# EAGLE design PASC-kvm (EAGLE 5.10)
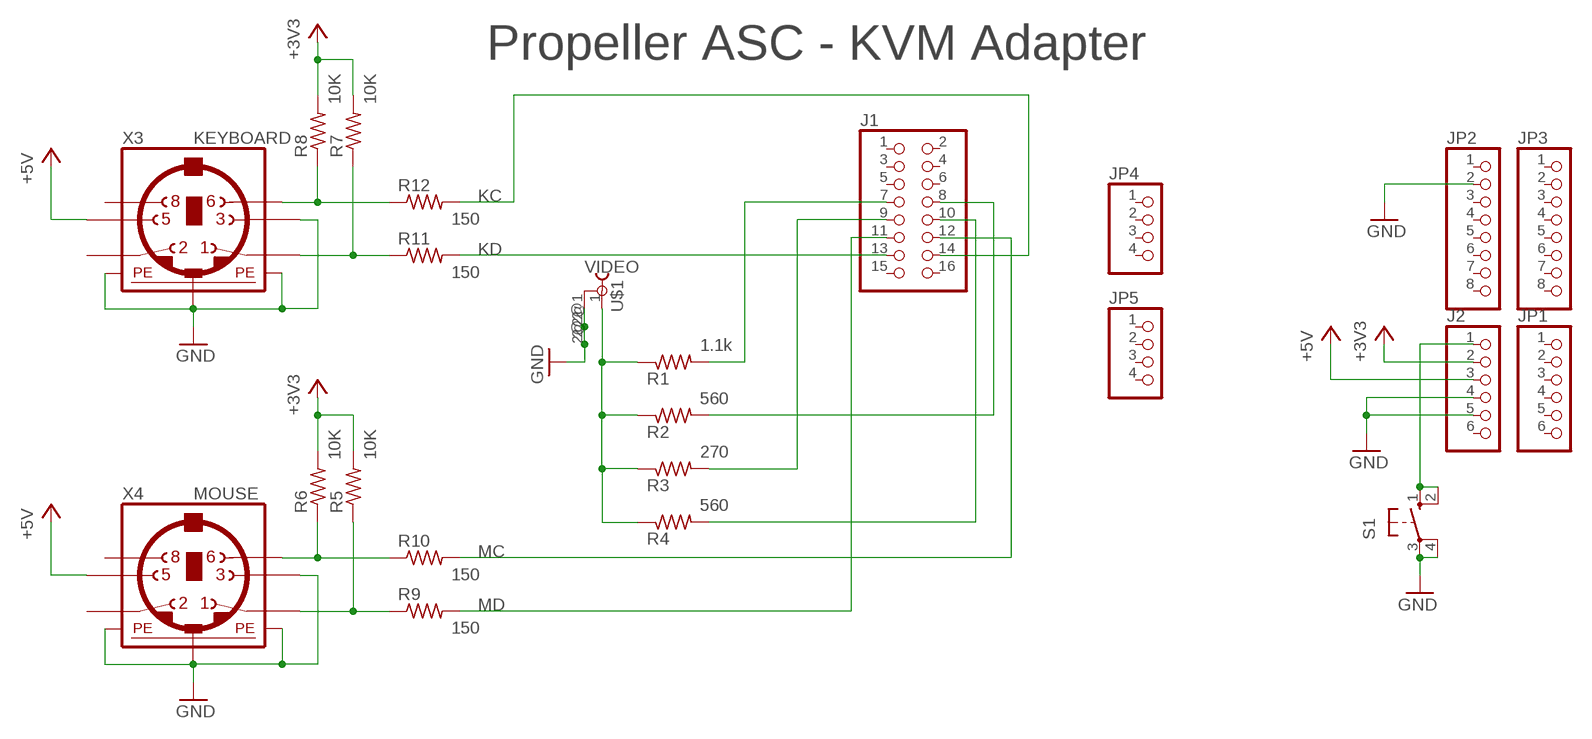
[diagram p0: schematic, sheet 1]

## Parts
J1  PINHD-2X8  [2X08]
J2  PINHD-1X6  [1X06]
JP1  PINHD-1X6  [1X06]
JP2  PINHD-1X8  [1X08]
JP3  PINHD-1X8  [1X08]
JP4  PINHD-1X4  [1X04]
JP5  PINHD-1X4  [1X04]
R1  1.1k  R-US_0207/10  [0207/10]
R2  560  R-US_0207/10  [0207/10]
R3  270  R-US_0207/10  [0207/10]
R4  560  R-US_0207/10  [0207/10]
R5  10K  R-US_0207/10  [0207/10]
R6  10K  R-US_0207/10  [0207/10]
R7  10K  R-US_0207/10  [0207/10]
R8  10K  R-US_0207/10  [0207/10]
R9  150  R-US_0207/10  [0207/10]
R10  150  R-US_0207/10  [0207/10]
R11  150  R-US_0207/10  [0207/10]
R12  150  R-US_0207/10  [0207/10]
S1  10-XX  [B3F-10XX]
U$1  VIDEO  RCA-RA  [RCA-RA]
X3  KEYBOARD  MINI_DIN_6  [M_DIN6]
X4  MOUSE  MINI_DIN_6  [M_DIN6]

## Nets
+3V3: J2.2 R5.2 R6.2 R7.2 R8.2
+5V: J2.3 X3.5 X4.5
GND: J2.4 J2.5 JP2.2 S1.3(P) S1.4(P1) U$1.2 U$1.2@1 U$1.2@2 X3.3 X3.SH1(PE1) X3.SH2(PE2) X3.SH3(PE3) X4.3 X4.SH1(PE1) X4.SH2(PE2) X4.SH3(PE3)
KC: J1.14 R12.2
KD: J1.13 R11.2
MC: J1.12 R10.2
MD: J1.11 R9.2
N$2: J1.10 R4.2
N$3: J1.8 R2.2
N$13: J1.9 R3.2
N$16: R1.1 R2.1 R3.1 R4.1 U$1.1
N$20: J1.7 R1.2
N$23: R8.1 R12.1 X3.6
N$24: R7.1 R11.1 X3.1
N$25: R6.1 R10.1 X4.6
N$27: R5.1 R9.1 X4.1
RESET: J2.1 S1.1(S) S1.2(S1)
Unconnected: J1.1 J1.2 J1.3 J1.4 J1.5 J1.6 J1.15 J1.16 J2.6 JP1.1 JP1.2 JP1.3 JP1.4 JP1.5 JP1.6 JP2.1 JP2.3 JP2.4 JP2.5 JP2.6 JP2.7 JP2.8 JP3.1 JP3.2 JP3.3 JP3.4 JP3.5 JP3.6 JP3.7 JP3.8 JP4.1 JP4.2 JP4.3 JP4.4 JP5.1 JP5.2 JP5.3 JP5.4 X3.2 X3.8 X4.2 X4.8

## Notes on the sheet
- Propeller ASC - KVM Adapter

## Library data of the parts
J1 = pinhead:PINHD-2X8: PIN HEADER
J2 JP1 = pinhead:PINHD-1X6: PIN HEADER
JP2 JP3 = pinhead:PINHD-1X8: PIN HEADER
JP4 JP5 = pinhead:PINHD-1X4: PIN HEADER
R1-R12 = rcl:R-US_: RESISTOR, American symbol
S1 = switch-omron:10-XX: OMRON SWITCH
U$1 = custom:RCA-RA
X3 X4 = mini_din:MINI_DIN_6

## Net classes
0 default: width 0.254 mm, drill 0.305 mm, clearance 0.152 mm
1 power: width 0.61 mm, drill 0.508 mm, clearance 0.152 mm
2 gnd: width 0.305 mm, drill 0.508 mm, clearance 0.152 mm
3 usbvcc: width 0.508 mm, drill 0.508 mm, clearance 0.152 mm
4 aref: width 0.406 mm

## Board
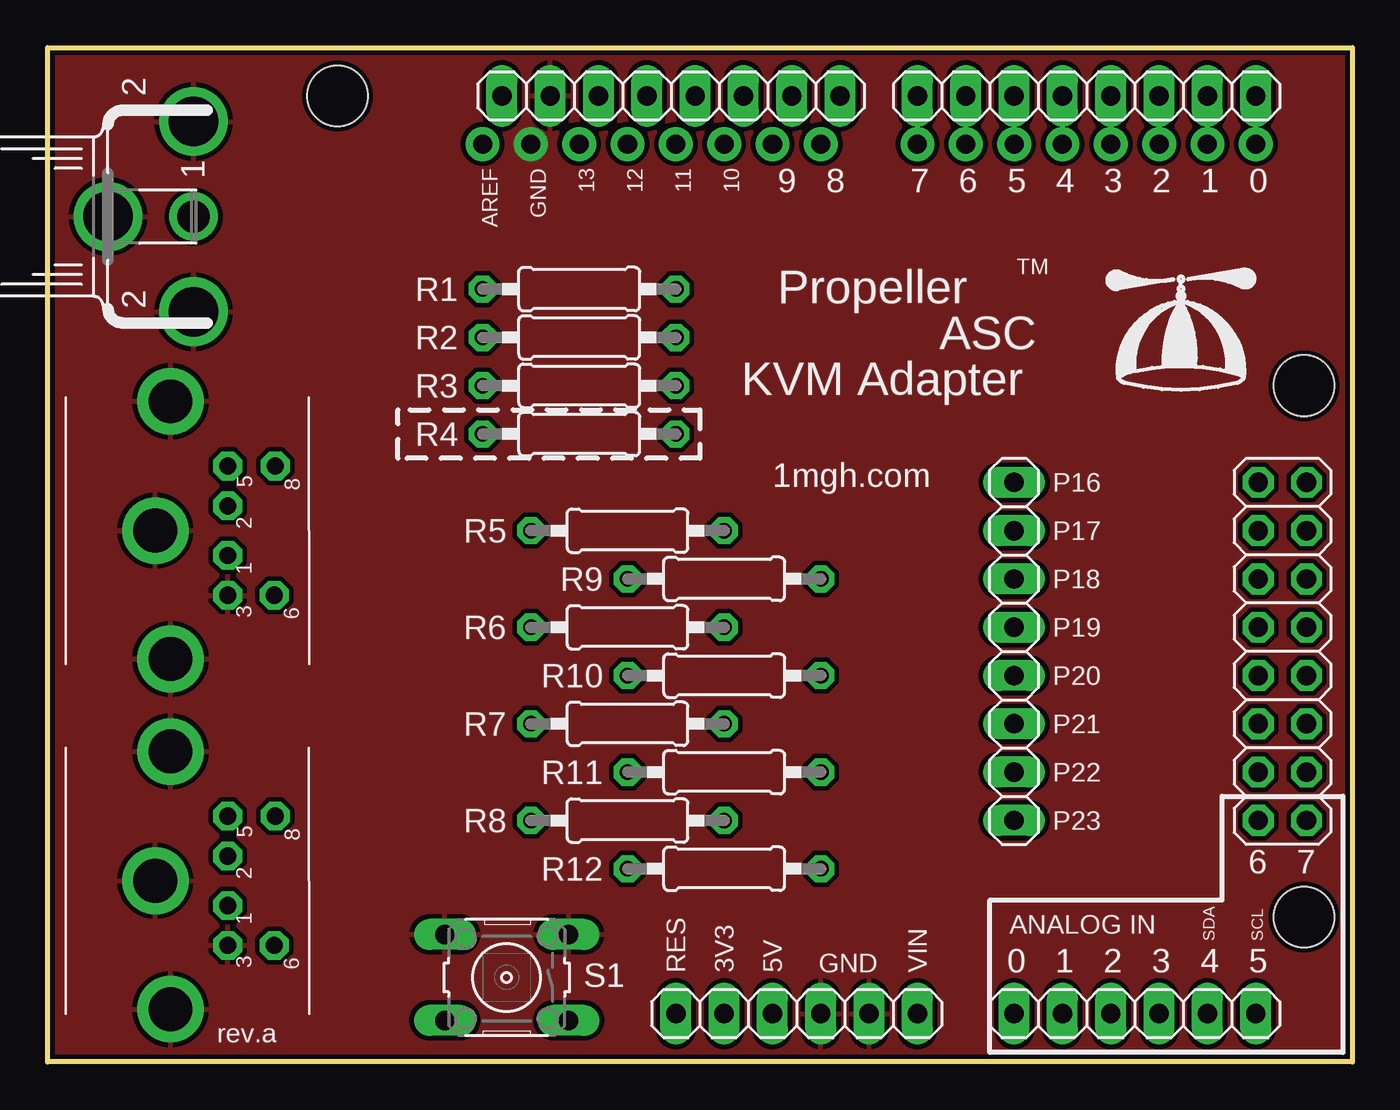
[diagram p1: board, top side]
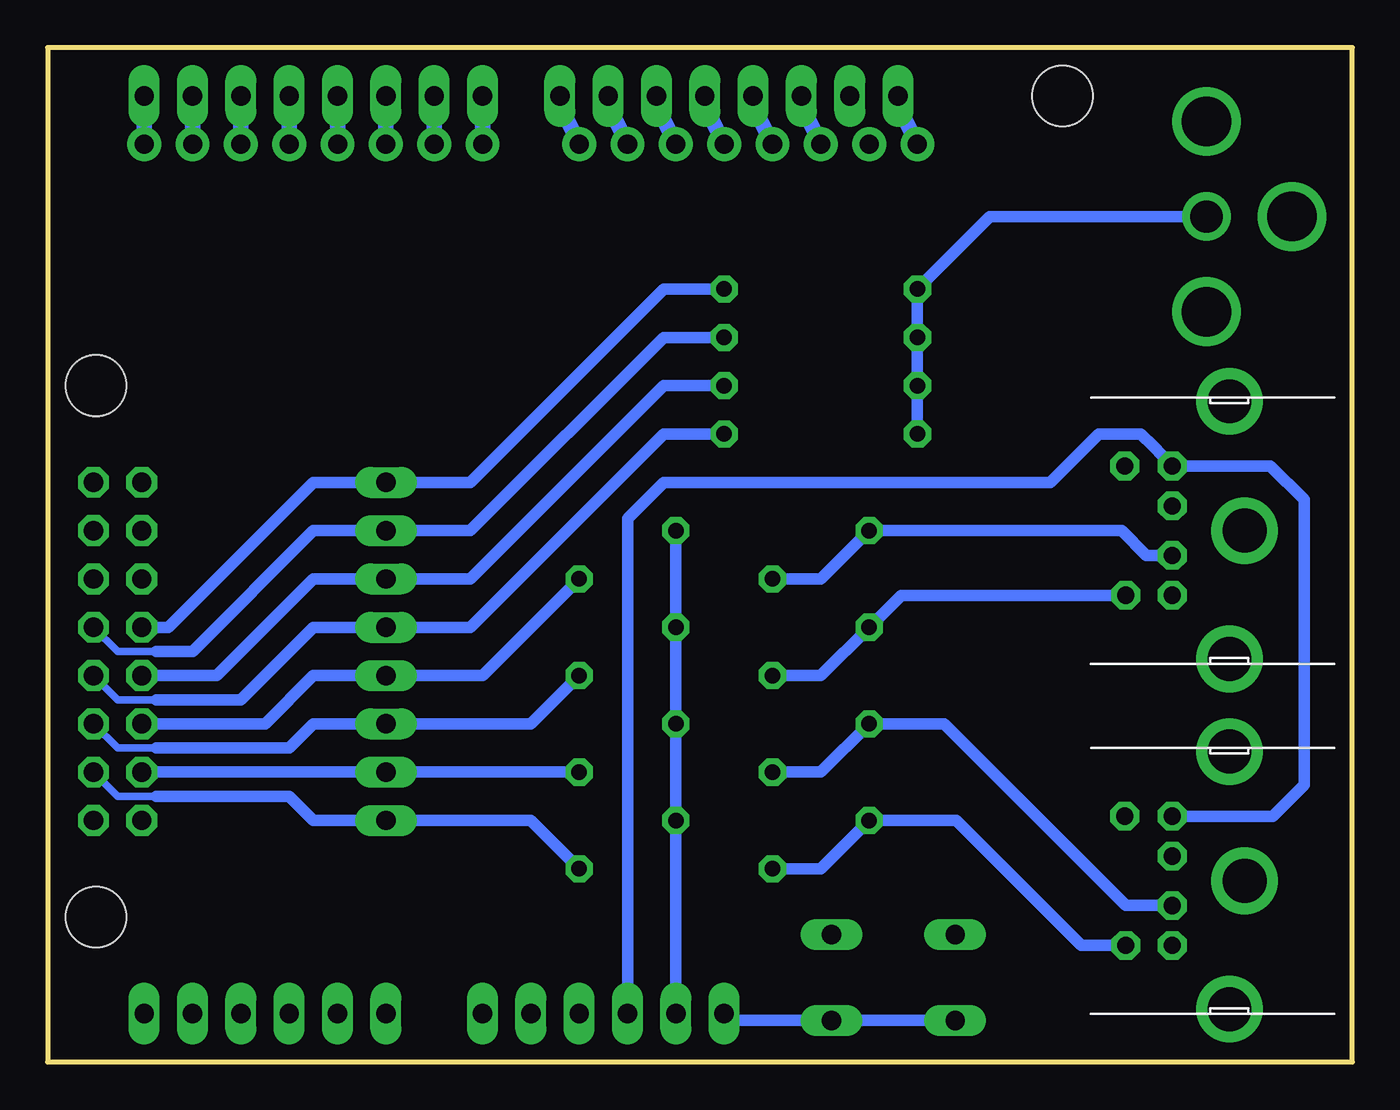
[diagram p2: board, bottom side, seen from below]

Size 68.58 x 53.34 mm. Coordinates in mm from the lower left corner, seen from the top.
Outline: 0,53.34 68.58,53.34 68.58,0 0,0 0,53.34
Copper layers (1*16): Top 0.035mm / dielectric 1.5mm / Bottom 0.035mm
Design rules "PcbFabEx": minimum track width 6mil, minimum drill 15mil, track to track 6mil, track to pad 6mil, pad to pad 6mil, via to via 6mil, smd to smd 6mil, copper to edge 10mil, drill to drill 8mil, minimum pad ring 12mil, minimum via ring 10mil, stop-mask expansion 4mil, vias tented up to drill 25mil, thermal gap 10mil
Holes 3.2 mm at 66.04,35.56 66.04,7.62 15.24,50.8

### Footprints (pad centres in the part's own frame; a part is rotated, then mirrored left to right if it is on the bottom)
2X08 = drill 1.016 octagon: 1 -8.89,-1.27; 2 -8.89,1.27; 3 -6.35,-1.27; 4 -6.35,1.27; 5 -3.81,-1.27; 6 -3.81,1.27; 7 -1.27,-1.27; 8 -1.27,1.27; 9 1.27,-1.27; 10 1.27,1.27; 11 3.81,-1.27; 12 3.81,1.27; 13 6.35,-1.27; 14 6.35,1.27; 15 8.89,-1.27; 16 8.89,1.27
1X06 = drill 1.016 long: 1 -6.35,0; 2 -3.81,0; 3 -1.27,0; 4 1.27,0; 5 3.81,0; 6 6.35,0
1X08 = drill 1.016 long: 1 -8.89,0; 2 -6.35,0; 3 -3.81,0; 4 -1.27,0; 5 1.27,0; 6 3.81,0; 7 6.35,0; 8 8.89,0
1X04 = drill 1.016 long: 1 -3.81,0; 2 -1.27,0; 3 1.27,0; 4 3.81,0
0207/10 = drill 0.813 octagon: 1 -5.08,0; 2 5.08,0
B3F-10XX = drill 1.016 long: 1 -3.251,2.261; 2 3.251,2.261; 3 -3.251,-2.261; 4 3.251,-2.261
RCA-RA = drill 1.7 round: 1 0,-4.5 | drill 2.6 round: 2 5,-4.5; 2@1 -5,-4.5; 2@2 0,0
M_DIN6 = drill 0.9 pad 1.422 octagon: 1 -1.3,-3.75; 2 1.3,-3.75; 3 -3.4,-3.75; 5 3.4,-3.75; 6 -3.4,-6.2; 8 3.4,-6.25 | drill 2.3 pad 3.5 round: SH1 6.8,-0.75; SH2 0,0.05; SH3 -6.75,-0.75

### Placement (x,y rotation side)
J1  64.9,21.59 270 top
J2  39.37,2.54 0 top
JP1  57.15,2.54 0 top
JP2  32.77,50.8 0 top
JP3  54.61,50.8 0 top
JP4  50.8,26.67 90 top
JP5  50.8,16.51 90 top
R1  27.94,40.64 0 top
R2  27.94,38.1 0 top
R3  27.94,35.56 0 top
R4  27.94,33.02 0 top
R5  30.48,27.94 0 top
R6  30.48,22.86 0 top
R7  30.48,17.78 0 top
R8  30.48,12.7 0 top
R9  35.56,25.4 0 top
R10  35.56,20.32 0 top
R11  35.56,15.24 0 top
R12  35.56,10.16 0 top
S1  24.13,4.45 180 top
U$1  3.17,44.45 90 top
U$2  [LOGOPROP]  59.56,38.61 0 top
X3  5.71,9.53 90 top
X4  5.71,27.94 90 top

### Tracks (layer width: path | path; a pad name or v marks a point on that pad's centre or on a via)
+3V3
  Bottom 0.61: J2.2 R8.2 R7.2 R6.2 R5.2
  Bottom 0.813: 35.56,1.91 J2.2
+5V
  Bottom 0.61: J2.3 38.1,28.57 36.2,30.48 15.88,30.48 13.34,33.02 11.12,33.02 10.48,32.38 X4.5 4.32,31.34 2.54,29.56 2.54,14.58 4.19,12.93 X3.5
  Bottom 0.813: J2.3 38.1,1.91
GND  (via drill 1 pad 1.78)
  other vias: 25.4,48.26
  pour Top (isolate 0.254): 0,53.34 0,0 68.58,0 68.58,53.34
KC
  Bottom 0.406: 62.87,13.97 64.9,13.97 J1.14
  Bottom 0.61: R12.2 43.18,12.7 54.61,12.7 55.88,13.97 62.87,13.97
KD
  Bottom 0.61: R11.2 J1.13
MC
  Bottom 0.406: 62.87,16.51 64.9,16.51 J1.12
  Bottom 0.61: R10.2 43.18,17.78 54.61,17.78 55.88,16.51 62.87,16.51
MD
  Bottom 0.61: R9.2 45.72,20.32 54.61,20.32 57.15,17.78 J1.11
N$2
  Bottom 0.406: 62.87,19.05 64.9,19.05 J1.10
  Bottom 0.61: R4.2 36.2,33.02 46.35,22.86 54.61,22.86 58.42,19.05 62.87,19.05
N$3
  Bottom 0.406: 62.87,21.59 64.9,21.59 J1.8
  Bottom 0.61: R2.2 36.2,38.1 46.35,27.94 54.61,27.94 60.96,21.59 62.87,21.59
N$4  (via drill 1 pad 1.78)
  Bottom 0.813: v45.72,48.26 45.72,51.44
N$5  (via drill 1 pad 1.78)
  Bottom 0.813: v48.26,48.26 48.26,51.44
N$6  (via drill 1 pad 1.78)
  Bottom 0.813: v50.8,48.26 50.8,51.44
N$7  (via drill 1 pad 1.78)
  Bottom 0.813: v53.34,48.26 53.34,51.44
N$8  (via drill 1 pad 1.78)
  Bottom 0.813: v55.88,48.26 55.88,51.44
N$9  (via drill 1 pad 1.78)
  Bottom 0.813: v58.42,48.26 58.42,51.44
N$10  (via drill 1 pad 1.78)
  Bottom 0.813: v60.96,48.26 60.96,51.44
N$11  (via drill 1 pad 1.78)
  Bottom 0.813: v63.5,48.26 63.5,51.44
N$12  (via drill 1 pad 1.78)
  Bottom 0.813: v40.64,48.26 41.91,50.8
N$13
  Bottom 0.61: R3.2 36.2,35.56 46.35,25.4 54.61,25.4 59.69,20.32 J1.9
N$14
  Bottom 0.813: 38.1,48.26 39.37,50.8
N$15  (via drill 1 pad 1.78)
  Bottom 0.813: v35.56,48.26 36.83,50.8
N$16
  Bottom 0.61: R4.1 R3.1 R2.1 R1.1 19.05,44.45 U$1.1
N$17  (via drill 1 pad 1.78)
  Bottom 0.813: v33.02,48.26 34.29,50.8
N$18  (via drill 1 pad 1.78)
  Bottom 0.813: v30.48,48.26 31.75,50.8
N$19  (via drill 1 pad 1.78)
  Bottom 0.813: v27.94,48.26 29.21,50.8
N$20
  Bottom 0.61: R1.2 36.2,40.64 46.35,30.48 54.61,30.48 62.23,22.86 J1.7
N$22  (via drill 1 pad 1.78)
  Bottom 0.813: v22.86,48.26 24.13,50.8
N$23
  Bottom 0.61: R12.1 27.94,10.16 R8.1 20.83,12.7 14.25,6.12 X3.6
N$24
  Bottom 0.61: R11.1 27.94,15.24 R7.1 21.46,17.78 11.91,8.22 X3.1
N$25
  Bottom 0.61: X4.6 23.72,24.54 R6.1 27.94,20.32 R10.1
N$27
  Bottom 0.61: X4.1 10.82,26.64 12.12,27.94 R5.1 27.94,25.4 R9.1
N$33  (via drill 1 pad 1.78)
  other vias: 38.1,48.26
RESET
  Bottom 0.61: 32.74,2.18 S1.1 S1.2
  Bottom 0.813: 32.74,2.18 J2.1

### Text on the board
tPlace: TM | Propeller | ASC | KVM Adapter | 1mgh.com | SDA | SCL | rev.a
tNames: AREF | GND | 13 | 12 | 11 | 10 | 9 | 8 | 7 | 6 | 5 | 4 | 3 | 2 | 1 | 0 | P16 | P17 | P18 | P19 | P20 | P21 | P22 | P23 | 6 | 7 | ANALOG IN | RES | 3V3 | 5V | GND | VIN | 0 | 1 | 2 | 3 | 4 | 5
